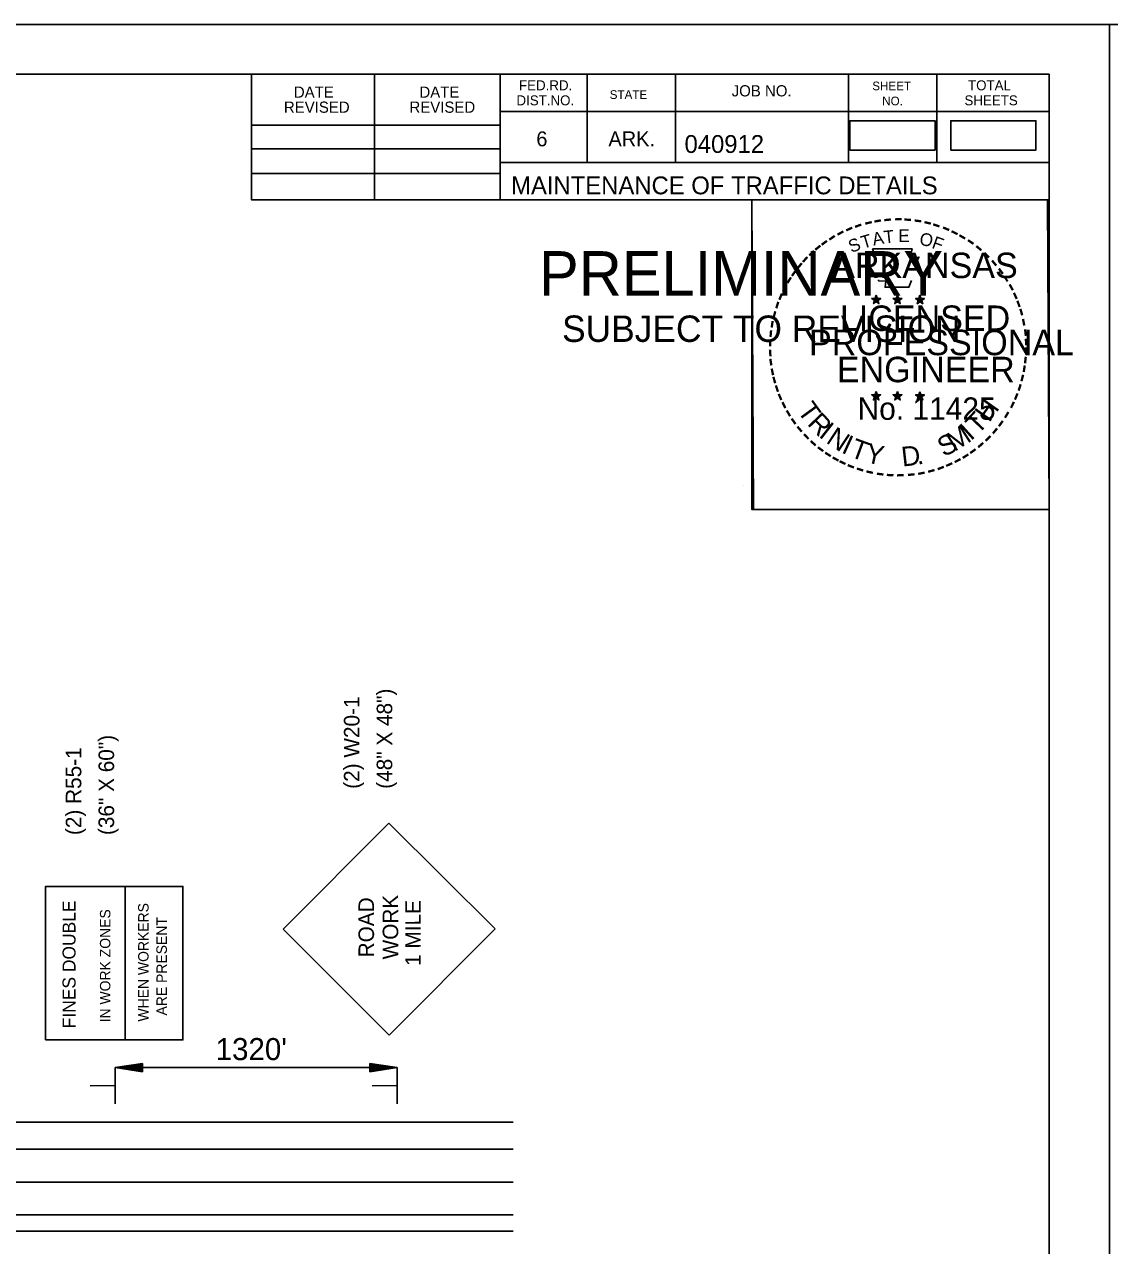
# Model space of a CAD drawing. Extents: x 13744624 to 13747958, y 3814079 to 3815145.
# Drawn here: x 13745864.8 to 13746290.9, y 3814665.8 to 3815145.4 of the extents above; entities that cross this region are included whole.
import ezdxf

# ---------------------------------------------------------------- set-up
doc = ezdxf.new("R2010")
doc.units = 0
for name, color, linetype in [('Default', 7, 'Continuous'), ('R_Border', 7, 'Continuous'), ('R_Border PE', 7, 'Continuous'), ('R_Border Prem', 7, 'Continuous'), ('R_Draft', 7, 'Continuous'), ('R_MOT', 7, 'Continuous'), ('R_No Plot', 7, 'Continuous')]:
    doc.layers.add(name, color=color, linetype=linetype)

msp = doc.modelspace()

# ---------------------------------------------------------------- linework, layer by layer
at = {"layer": 'Default'}
for p, q in [((13745900.44, 3814735.66), (13746007.59, 3814735.66)), ((13746011.16, 3814735.66), (13745900.44, 3814735.66)), ((13746056.77, 3814714.29), (13745462.99, 3814714.29)), ((13746056.77, 3814703.57), (13745462.99, 3814703.57)), ((13746056.77, 3814690.71), (13745462.99, 3814690.71)), ((13746056.77, 3814677.86), (13745462.99, 3814677.86)), ((13746056.77, 3814671.43), (13745462.99, 3814671.43))]:
    msp.add_line(p, q, dxfattribs=at)
for points in [[(13746188.98, 3815096.03), (13746222.4, 3815096.03), (13746222.4, 3815107.58), (13746188.98, 3815107.58)], [(13746228.55, 3815096.03), (13746261.97, 3815096.03), (13746261.97, 3815107.58), (13746228.55, 3815107.58)]]:
    msp.add_lwpolyline(points, close=True, dxfattribs=at)
at = {"layer": 'R_Border'}
for p, q in [((13744686.23, 3815125.92), (13746267.13, 3815125.92)), ((13745953.93, 3815076.52), (13745953.93, 3815125.92)), ((13746002.33, 3815076.52), (13746002.33, 3815125.92)), ((13746051.63, 3815125.92), (13746051.63, 3815076.52)), ((13746085.83, 3815125.92), (13746085.83, 3815091.22)), ((13746120.53, 3815125.92), (13746120.53, 3815091.22)), ((13746188.43, 3815125.92), (13746188.43, 3815091.22)), ((13746223.13, 3815125.92), (13746223.13, 3815091.22)), ((13746267.13, 3814098.62), (13746267.13, 3815125.92)), ((13746267.13, 3815111.22), (13746051.63, 3815111.22)), ((13746267.13, 3815111.32), (13746267.13, 3815111.32)), ((13745953.93, 3815105.82), (13746051.63, 3815105.82)), ((13745953.93, 3815096.52), (13746051.63, 3815096.52)), ((13746267.13, 3815091.22), (13746051.63, 3815091.22)), ((13746066.43, 3815091.22), (13746267.13, 3815091.22)), ((13745953.93, 3815086.82), (13746051.63, 3815086.82)), ((13746267.13, 3815076.52), (13745953.93, 3815076.52))]:
    msp.add_line(p, q, dxfattribs=at)
at = {"layer": 'R_Border PE'}
for p, q in [((13746197.55, 3815037.8), (13746199.3, 3815037.24)), ((13746197.55, 3815037.8), (13746198.82, 3815037.57)), ((13746197.55, 3815037.8), (13746198.74, 3815037.19)), ((13746198.22, 3815035.76), (13746199.3, 3815037.24)), ((13746198.22, 3815035.76), (13746198.85, 3815036.98)), ((13746198.22, 3815035.76), (13746199.29, 3815036.84)), ((13746199.3, 3815039.07), (13746199.09, 3815037.81)), ((13746200.36, 3815035.76), (13746199.29, 3815036.83)), ((13746199.3, 3815037.24), (13746199.3, 3815039.07)), ((13746199.3, 3815039.07), (13746199.54, 3815037.82)), ((13746201.03, 3815037.8), (13746199.3, 3815037.24)), ((13746200.36, 3815035.76), (13746199.3, 3815037.24)), ((13746201.03, 3815037.8), (13746199.6, 3815037.55)), ((13746200.36, 3815035.76), (13746199.68, 3815037.21)), ((13746201.03, 3815037.8), (13746200.01, 3815037.29)), ((13746205.9, 3815037.8), (13746207.65, 3815037.24)), ((13746205.9, 3815037.8), (13746207.17, 3815037.57)), ((13746205.9, 3815037.8), (13746207.09, 3815037.19)), ((13746206.57, 3815035.76), (13746207.65, 3815037.24)), ((13746206.57, 3815035.76), (13746207.2, 3815036.98)), ((13746206.57, 3815035.76), (13746207.64, 3815036.84)), ((13746207.65, 3815039.07), (13746207.44, 3815037.81)), ((13746208.71, 3815035.76), (13746207.64, 3815036.83)), ((13746207.65, 3815037.24), (13746207.65, 3815039.07)), ((13746207.65, 3815039.07), (13746207.89, 3815037.82)), ((13746209.38, 3815037.8), (13746207.65, 3815037.24)), ((13746208.71, 3815035.76), (13746207.65, 3815037.24)), ((13746209.38, 3815037.8), (13746207.95, 3815037.55)), ((13746208.71, 3815035.76), (13746208.03, 3815037.21)), ((13746209.38, 3815037.8), (13746208.36, 3815037.29)), ((13746214.72, 3815037.74), (13746216.47, 3815037.18)), ((13746214.72, 3815037.74), (13746215.99, 3815037.51)), ((13746214.72, 3815037.74), (13746215.91, 3815037.13)), ((13746215.39, 3815035.7), (13746216.47, 3815037.18)), ((13746215.39, 3815035.7), (13746216.02, 3815036.92)), ((13746215.39, 3815035.7), (13746216.46, 3815036.78)), ((13746216.47, 3815039.01), (13746216.26, 3815037.75)), ((13746217.53, 3815035.7), (13746216.46, 3815036.77)), ((13746216.47, 3815037.18), (13746216.47, 3815039.01)), ((13746216.47, 3815039.01), (13746216.71, 3815037.76)), ((13746218.2, 3815037.74), (13746216.47, 3815037.18)), ((13746217.53, 3815035.7), (13746216.47, 3815037.18)), ((13746218.2, 3815037.74), (13746216.77, 3815037.49)), ((13746217.53, 3815035.7), (13746216.85, 3815037.15)), ((13746218.2, 3815037.74), (13746217.18, 3815037.23)), ((13746197.53, 3814999.93), (13746199.28, 3814999.38)), ((13746197.53, 3814999.93), (13746198.8, 3814999.71)), ((13746197.53, 3814999.93), (13746198.72, 3814999.32)), ((13746198.2, 3814997.89), (13746199.28, 3814999.38)), ((13746198.2, 3814997.89), (13746198.83, 3814999.11)), ((13746198.2, 3814997.89), (13746199.27, 3814998.98)), ((13746199.28, 3815001.2), (13746199.07, 3814999.94)), ((13746200.34, 3814997.89), (13746199.27, 3814998.96)), ((13746199.28, 3814999.38), (13746199.28, 3815001.2)), ((13746199.28, 3815001.2), (13746199.52, 3814999.95)), ((13746201.01, 3814999.93), (13746199.28, 3814999.38)), ((13746200.34, 3814997.89), (13746199.28, 3814999.38)), ((13746201.01, 3814999.93), (13746199.58, 3814999.69)), ((13746200.34, 3814997.89), (13746199.66, 3814999.35)), ((13746201.01, 3814999.93), (13746199.99, 3814999.42)), ((13746205.88, 3814999.93), (13746207.62, 3814999.38)), ((13746205.88, 3814999.93), (13746207.14, 3814999.71)), ((13746205.88, 3814999.93), (13746207.06, 3814999.32)), ((13746206.54, 3814997.89), (13746207.62, 3814999.38)), ((13746206.54, 3814997.89), (13746207.17, 3814999.11)), ((13746206.54, 3814997.89), (13746207.61, 3814998.98)), ((13746207.62, 3815001.2), (13746207.42, 3814999.94)), ((13746208.69, 3814997.89), (13746207.61, 3814998.96)), ((13746207.62, 3814999.38), (13746207.62, 3815001.2)), ((13746207.62, 3815001.2), (13746207.87, 3814999.95)), ((13746209.36, 3814999.93), (13746207.62, 3814999.38)), ((13746208.69, 3814997.89), (13746207.62, 3814999.38)), ((13746209.36, 3814999.93), (13746207.93, 3814999.69)), ((13746208.69, 3814997.89), (13746208, 3814999.35)), ((13746209.36, 3814999.93), (13746208.34, 3814999.42)), ((13746214.71, 3814999.88), (13746216.46, 3814999.33)), ((13746214.71, 3814999.88), (13746215.98, 3814999.66)), ((13746214.71, 3814999.88), (13746215.9, 3814999.27)), ((13746215.38, 3814997.84), (13746216.46, 3814999.33)), ((13746215.38, 3814997.84), (13746216.01, 3814999.06)), ((13746215.38, 3814997.84), (13746216.45, 3814998.93)), ((13746216.46, 3815001.15), (13746216.25, 3814999.89)), ((13746217.52, 3814997.84), (13746216.45, 3814998.91)), ((13746216.46, 3814999.33), (13746216.46, 3815001.15)), ((13746216.46, 3815001.15), (13746216.7, 3814999.9)), ((13746218.19, 3814999.88), (13746216.46, 3814999.33)), ((13746217.52, 3814997.84), (13746216.46, 3814999.33)), ((13746218.19, 3814999.88), (13746216.76, 3814999.64)), ((13746217.52, 3814997.84), (13746216.84, 3814999.3)), ((13746218.19, 3814999.88), (13746217.17, 3814999.37))]:
    msp.add_line(p, q, dxfattribs=at)
for points in [[(13746197.76, 3815057.19), (13746199.1, 3815053.05)], [(13746215.31, 3815052.58), (13746216.02, 3815054), (13746212.6, 3815053.88), (13746213.34, 3815057.19), (13746197.76, 3815057.19)], [(13746200.22, 3815045.07), (13746200.22, 3815044.64), (13746203.03, 3815044.54), (13746202.76, 3815042.18), (13746212.11, 3815042.18), (13746213.12, 3815044.86)], [(13746199.3, 3815039.07), (13746200.36, 3815035.76), (13746197.55, 3815037.8), (13746201.03, 3815037.8), (13746198.22, 3815035.76), (13746199.3, 3815039.07)], [(13746207.65, 3815039.07), (13746208.71, 3815035.76), (13746205.9, 3815037.8), (13746209.38, 3815037.8), (13746206.57, 3815035.76), (13746207.65, 3815039.07)], [(13746216.47, 3815039.01), (13746217.53, 3815035.7), (13746214.72, 3815037.74), (13746218.2, 3815037.74), (13746215.39, 3815035.7), (13746216.47, 3815039.01)], [(13746199.28, 3815001.2), (13746200.34, 3814997.89), (13746197.53, 3814999.93), (13746201.01, 3814999.93), (13746198.2, 3814997.89), (13746199.28, 3815001.2)], [(13746207.62, 3815001.2), (13746208.69, 3814997.89), (13746205.88, 3814999.93), (13746209.36, 3814999.93), (13746206.54, 3814997.89), (13746207.62, 3815001.2)], [(13746216.46, 3815001.15), (13746217.52, 3814997.84), (13746214.71, 3814999.88), (13746218.19, 3814999.88), (13746215.38, 3814997.84), (13746216.46, 3815001.15)]]:
    msp.add_lwpolyline(points, dxfattribs=at)
for centre, radius in [((13746199.29, 3815037.24), 0.861), ((13746199.29, 3815037.24), 0.723), ((13746199.29, 3815037.24), 0.579), ((13746199.29, 3815037.24), 0.495), ((13746199.29, 3815037.24), 0.374), ((13746199.29, 3815037.24), 0.248), ((13746199.29, 3815037.24), 0.148), ((13746207.64, 3815037.24), 0.861), ((13746207.64, 3815037.24), 0.723), ((13746207.64, 3815037.24), 0.579), ((13746207.64, 3815037.24), 0.495), ((13746207.64, 3815037.24), 0.374), ((13746207.64, 3815037.24), 0.248), ((13746207.64, 3815037.24), 0.148), ((13746216.46, 3815037.18), 0.861), ((13746216.46, 3815037.18), 0.723), ((13746216.46, 3815037.18), 0.579), ((13746216.46, 3815037.18), 0.495), ((13746216.46, 3815037.18), 0.374), ((13746216.46, 3815037.18), 0.248), ((13746216.46, 3815037.18), 0.148), ((13746199.27, 3814999.37), 0.861), ((13746199.27, 3814999.37), 0.723), ((13746199.27, 3814999.37), 0.579), ((13746199.27, 3814999.37), 0.495), ((13746199.27, 3814999.37), 0.374), ((13746199.27, 3814999.37), 0.248), ((13746199.27, 3814999.37), 0.148), ((13746207.62, 3814999.37), 0.861), ((13746207.62, 3814999.37), 0.723), ((13746207.62, 3814999.37), 0.579), ((13746207.62, 3814999.37), 0.495), ((13746207.62, 3814999.37), 0.374), ((13746207.62, 3814999.37), 0.248), ((13746207.62, 3814999.37), 0.148), ((13746216.45, 3814999.32), 0.861), ((13746216.45, 3814999.32), 0.723), ((13746216.45, 3814999.32), 0.579), ((13746216.45, 3814999.32), 0.495), ((13746216.45, 3814999.32), 0.374), ((13746216.45, 3814999.32), 0.248), ((13746216.45, 3814999.32), 0.148)]:
    msp.add_circle(centre, radius, dxfattribs=at)
at = {"layer": 'R_Draft'}
for p, q in [((13745911.16, 3814737.27), (13745900.44, 3814735.66)), ((13745911.16, 3814734.05), (13745900.44, 3814735.66)), ((13745911.16, 3814737), (13745902.23, 3814735.66)), ((13745911.16, 3814734.32), (13745902.23, 3814735.66)), ((13745911.16, 3814736.73), (13745904.08, 3814735.66)), ((13745911.16, 3814734.59), (13745904.08, 3814735.66)), ((13745911.16, 3814736.46), (13745905.86, 3814735.66)), ((13745911.16, 3814734.86), (13745905.86, 3814735.66)), ((13745911.16, 3814736.18), (13745907.68, 3814735.66)), ((13745911.16, 3814735.14), (13745907.68, 3814735.66)), ((13745911.16, 3814735.91), (13745909.46, 3814735.66)), ((13745911.16, 3814735.41), (13745909.46, 3814735.66)), ((13745911.16, 3814734.05), (13745911.16, 3814737.27)), ((13746000.44, 3814737.27), (13746011.16, 3814735.66)), ((13746000.44, 3814737.27), (13746000.44, 3814734.05)), ((13746000.44, 3814737), (13746009.37, 3814735.66)), ((13746000.44, 3814736.73), (13746007.53, 3814735.66)), ((13746000.44, 3814736.46), (13746005.74, 3814735.66)), ((13746000.44, 3814736.18), (13746003.93, 3814735.66)), ((13746000.44, 3814735.91), (13746002.14, 3814735.66)), ((13746000.44, 3814734.05), (13746011.16, 3814735.66)), ((13746000.44, 3814735.13), (13746003.93, 3814735.66)), ((13746000.44, 3814734.59), (13746007.53, 3814735.66)), ((13746000.44, 3814734.32), (13746009.37, 3814735.66)), ((13746000.44, 3814734.86), (13746005.74, 3814735.66)), ((13746000.44, 3814735.41), (13746002.14, 3814735.66))]:
    msp.add_line(p, q, dxfattribs=at)
at = {"layer": 'R_MOT'}
for p, q in [((13746007.92, 3814831.7), (13745966.41, 3814790.01)), ((13746007.92, 3814831.7), (13746049.61, 3814790.15)), ((13745904.42, 3814806.85), (13745904.42, 3814746.55)), ((13745966.41, 3814790.01), (13746008.07, 3814748.46)), ((13746049.61, 3814790.15), (13746008.07, 3814748.46)), ((13745900.44, 3814735.66), (13745900.51, 3814721.48)), ((13746011.16, 3814735.66), (13746011.22, 3814721.48)), ((13745900.48, 3814728.6), (13745890.59, 3814728.56)), ((13746011.19, 3814728.6), (13746001.3, 3814728.56))]:
    msp.add_line(p, q, dxfattribs=at)
msp.add_lwpolyline([(13745873.16, 3814746.55), (13745927.05, 3814746.55), (13745927.05, 3814806.85), (13745873.16, 3814806.85)], close=True, dxfattribs=at)
at = {"layer": 'R_No Plot'}
for p, q in [((13744624.22, 3815145.39), (13746290.89, 3815145.39)), ((13746147.3, 3814964.24), (13746147.3, 3814964.24))]:
    msp.add_line(p, q, dxfattribs=at)
for points in [[(13744624.19, 3815145.39), (13746290.89, 3815145.39), (13746290.89, 3814078.71), (13744624.19, 3814078.71)], [(13746290.89, 3815145.39), (13747957.59, 3815145.39), (13747957.59, 3814078.71), (13746290.89, 3814078.71)], [(13745855.83, 3815125.92), (13745953.93, 3815125.92), (13745953.93, 3815076.52), (13746034.49, 3815076.52), (13746150.48, 3815076.52), (13746150.48, 3814954.86), (13746267.13, 3814954.86), (13746267.13, 3814098.62), (13744686.23, 3814098.62), (13744686.23, 3815125.92)], [(13746150.48, 3815076.52), (13746266.52, 3815076.52), (13746267.13, 3814954.86), (13746151.09, 3814954.86)]]:
    msp.add_lwpolyline(points, close=True, dxfattribs=at)

# ---------------------------------------------------------------- texts
at = {"layer": 'Default'}
msp.add_text("1320'", height=8.664, dxfattribs=at).set_placement((13745939.91, 3814738.6))
at = {"layer": 'R_Border'}
for s, height, p in [('FED.RD.', 3.91, (13746059.03, 3815119.52)), ('SHEET', 3.42, (13746197.73, 3815119.52)), ('TOTAL', 3.91, (13746235.33, 3815119.52)), ('DATE', 4.396, (13745970.62, 3815116.6)), ('DATE', 4.396, (13746019.92, 3815116.6)), ('DIST.NO.', 3.91, (13746058.03, 3815113.62)), ('STATE', 3.42, (13746094.63, 3815116.12)), ('JOB NO.', 4.396, (13746142.53, 3815117.12)), ('NO.', 3.42, (13746201.63, 3815113.62)), ('SHEETS', 3.91, (13746233.93, 3815113.62)), ('REVISED', 4.396, (13745966.72, 3815110.7)), ('REVISED', 4.396, (13746016.02, 3815110.7)), ('6', 5.86, (13746065.83, 3815097.52)), ('ARK.', 5.861, (13746094.13, 3815097.52)), ('040912', 7, (13746124.01, 3815094.92)), ('MAINTENANCE OF TRAFFIC DETAILS', 7, (13746055.94, 3815078.67))]:
    msp.add_text(s, height=height, dxfattribs=at).set_placement(p)
at = {"layer": 'R_Border PE'}
for s, height, rotation, p in [('-', 8, 5.8968, (13746202.28, 3815065.39)), ('-', 8, 0.1862, (13746206.14, 3815065.75)), ('-', 8, 357.743, (13746209.76, 3815065.68)), ('-', 8, 28.7918, (13746185.16, 3815059.89)), ('-', 8, 24.3072, (13746188.33, 3815061.48)), ('-', 8, 19.1761, (13746191.5, 3815062.82)), ('-', 8, 13.6302, (13746195.25, 3815064.03)), ('-', 8, 10.2193, (13746198.64, 3815064.84)), ('T', 5, 6.0228, (13746202.48, 3815059.32)), ('E', 5, 0.8323, (13746208, 3815059.87)), ('-', 8, 352.1617, (13746213.48, 3815065.4)), ('-', 8, 347.2049, (13746217.07, 3815064.83)), ('-', 8, 342.3362, (13746220.25, 3815064.06)), ('-', 8, 337.8551, (13746223.92, 3815062.94)), ('-', 8, 334.1211, (13746227.08, 3815061.59)), ('-', 8, 36.2317, (13746179.29, 3815056.07)), ('-', 8, 34.0636, (13746182.18, 3815058.04)), ('S', 5, 21.594, (13746189.53, 3815055.58)), ('T', 5, 16.4036, (13746194.1, 3815057.23)), ('A', 5, 11.2132, (13746198.23, 3815058.49)), ('O', 5, 350.4515, (13746216.02, 3815058.82)), ('F', 5, 340.0707, (13746220.79, 3815057.68)), ('-', 8, 329.6409, (13746229.97, 3815060.17)), ('-', 8, 325.8627, (13746233.19, 3815058.37)), ('-', 8, 42.9622, (13746174.74, 3815052.09)), ('-', 8, 38.9507, (13746176.91, 3815054.18)), ('-', 8, 320.5297, (13746236.24, 3815056.24)), ('-', 8, 315.5786, (13746239.23, 3815053.8)), ('-', 8, 50.6142, (13746170.49, 3815047.27)), ('-', 8, 48.4231, (13746172.5, 3815049.7)), ('-', 8, 309.8797, (13746242.08, 3815051.05)), ('-', 8, 58.0706, (13746166.8, 3815041.8)), ('-', 8, 54.2325, (13746168.42, 3815044.44)), ('-', 8, 306.6522, (13746244.7, 3815048.04)), ('-', 7, 303.6753, (13746247.13, 3815045.2)), ('-', 8, 62.8713, (13746165.23, 3815038.73)), ('-', 8, 299.6684, (13746248.73, 3815042.16)), ('-', 8, 72.3945, (13746162.84, 3815032.53)), ('-', 8, 67.7743, (13746163.94, 3815035.68)), ('-', 8, 294.6628, (13746250.35, 3815039.1)), ('-', 8, 290.5728, (13746251.63, 3815036.22)), ('-', 8, 75.461, (13746161.86, 3815028.96)), ('-', 8, 285.1233, (13746252.8, 3815033.32)), ('-', 8, 81.2013, (13746161.2, 3815025.39)), ('-', 8, 280.5493, (13746253.8, 3815029.61)), ('-', 8, 89.0622, (13746160.69, 3815018.43)), ('-', 8, 85.1863, (13746160.82, 3815021.94)), ('-', 8, 276.5962, (13746254.61, 3815025.77)), ('-', 8, 274.3301, (13746254.91, 3815022.16)), ('-', 8, 94.1959, (13746160.87, 3815014.81)), ('-', 8, 269.9407, (13746255.08, 3815019)), ('-', 8, 98.9479, (13746161.23, 3815011.47)), ('-', 8, 263.5172, (13746254.99, 3815015.67)), ('-', 8, 101.7149, (13746161.9, 3815007.81)), ('-', 8, 105.4578, (13746162.71, 3815004.83)), ('-', 8, 255.7626, (13746254.08, 3815009.01)), ('-', 8, 260.9953, (13746254.63, 3815012.4)), ('-', 8, 109.0874, (13746163.79, 3815001.68)), ('-', 8, 252.8681, (13746253.18, 3815005.41)), ('-', 8, 114.0643, (13746165.06, 3814998.7)), ('-', 8, 115.7289, (13746166.58, 3814995.61)), ('T', 7.7, 306.0406, (13746168.07, 3814993.57)), ('H', 7.7, 54.6088, (13746243.68, 3814988.74)), ('-', 8, 244.6197, (13746250.75, 3814998.9)), ('-', 8, 247.8887, (13746252.06, 3815002.04)), ('-', 8, 120.4471, (13746168.37, 3814992.68)), ('R', 7.7, 314.005, (13746171.89, 3814988.33)), ('T', 7.7, 46.6444, (13746239.23, 3814984.03)), ('-', 8, 239.0712, (13746248.78, 3814995.14)), ('-', 8, 125.8934, (13746170.38, 3814989.87)), ('-', 8, 130.7181, (13746172.69, 3814987.11)), ('I', 7.7, 321.9694, (13746176.39, 3814983.67)), ('M', 7.7, 32.6563, (13746230, 3814977.4)), ('I', 7.7, 42.1136, (13746236.42, 3814981.64)), ('-', 8, 233.8452, (13746246.77, 3814991.87)), ('-', 8, 134.2238, (13746175.28, 3814984.39)), ('N', 7.7, 326.5002, (13746179.23, 3814981.31)), ('I', 7.7, 335.3603, (13746185.27, 3814977.38)), ('T', 7.7, 339.8912, (13746188.57, 3814975.74)), ('S', 7.7, 26.9312, (13746225.8, 3814975.38)), ('-', 8, 225.7653, (13746242.23, 3814986.22)), ('-', 8, 231.2538, (13746244.62, 3814989.04)), ('-', 8, 138.9338, (13746177.9, 3814982.07)), ('-', 8, 144.6463, (13746180.68, 3814980.04)), ('Y', 7.7, 347.8556, (13746194.66, 3814973.52)), ('D', 7.7, 6.3969, (13746209.58, 3814971.72)), ('-', 8, 215.7363, (13746236.87, 3814981.32)), ('-', 8, 221.0851, (13746239.62, 3814983.68)), ('-', 8, 148.0898, (13746183.49, 3814978.18)), ('-', 8, 151.5704, (13746186.38, 3814976.56)), ('-', 8, 154.6002, (13746188.99, 3814975.32)), ('.', 7.7, 13.7642, (13746215.54, 3814972.36)), ('-', 8, 204.2516, (13746228.29, 3814976.06)), ('-', 8, 207.3568, (13746231.41, 3814977.65)), ('-', 8, 212.2491, (13746234.2, 3814979.38)), ('-', 8, 158.5612, (13746192.11, 3814974.05)), ('-', 8, 162.7983, (13746195.55, 3814972.99)), ('-', 8, 167.5555, (13746199.12, 3814972.17)), ('-', 8, 173.1155, (13746202.98, 3814971.62)), ('-', 8, 176.5183, (13746206.72, 3814971.35)), ('-', 8, 181.5918, (13746210.44, 3814971.45)), ('-', 8, 185.8167, (13746214.49, 3814971.83)), ('-', 8, 191.2858, (13746218.17, 3814972.49)), ('-', 8, 195.4743, (13746221.81, 3814973.48)), ('-', 8, 200.7184, (13746225.2, 3814974.69))]:
    msp.add_text(s, height=height, rotation=rotation, dxfattribs=at).set_placement(p)
for s, height, p in [('ARKANSAS', 10, (13746182.02, 3815045.75)), ('DWB', 0.05, (13746199.23, 3815037.21)), ('DWB', 0.05, (13746207.58, 3815037.21)), ('DWB', 0.05, (13746216.4, 3815037.16)), ('LICENSED', 10, (13746185.01, 3815025)), ('PROFESSIONAL', 10, (13746172.89, 3815015.48)), ('ENGINEER', 10, (13746183.83, 3815004.86)), ('No. 11425', 8.785, (13746191.96, 3814990.1)), ('DWB', 0.05, (13746199.21, 3814999.35)), ('DWB', 0.05, (13746207.56, 3814999.35)), ('DWB', 0.05, (13746216.39, 3814999.3))]:
    msp.add_text(s, height=height, dxfattribs=at).set_placement(p)
at = {"layer": 'R_Border Prem'}
for s, height, p in [('PRELIMINARY', 17.5, (13746066.88, 3815038.84)), ('DWB', 0.05, (13746070.62, 3815048.08)), ('SUBJECT TO REVISION', 10.3756, (13746075.93, 3815020.69))]:
    msp.add_text(s, height=height, dxfattribs=at).set_placement(p)
at = {"layer": 'R_MOT'}
for s, height, rotation, p in [('(48" X 48")', 6.1, 90, (13746009.24, 3814845.17)), ('(2) W20-1', 6.1, 90, (13745996.38, 3814845.17)), ('(36" X 60")', 6.1, 90, (13745900.02, 3814827)), ('(2) R55-1', 6.1, 90, (13745887.16, 3814827)), ('FINES DOUBLE', 5.1171, 90, (13745884.9, 3814751.11)), ('ROAD', 6.1, 90.1004, (13746002.1, 3814778.97)), ('WORK', 6.1, 90.1003, (13746011.61, 3814778.17)), (' 1 MILE', 6.1, 90.0995, (13746020.47, 3814773.36)), ('IN WORK ZONES', 4.093, 90, (13745898.57, 3814753.45)), ('WHEN WORKERS', 4.0939, 90, (13745913.57, 3814753.76)), ('ARE PRESENT', 4.0939, 90, (13745920.75, 3814756.13))]:
    msp.add_text(s, height=height, rotation=rotation, dxfattribs=at).set_placement(p)

doc.saveas('drawing.dxf')
